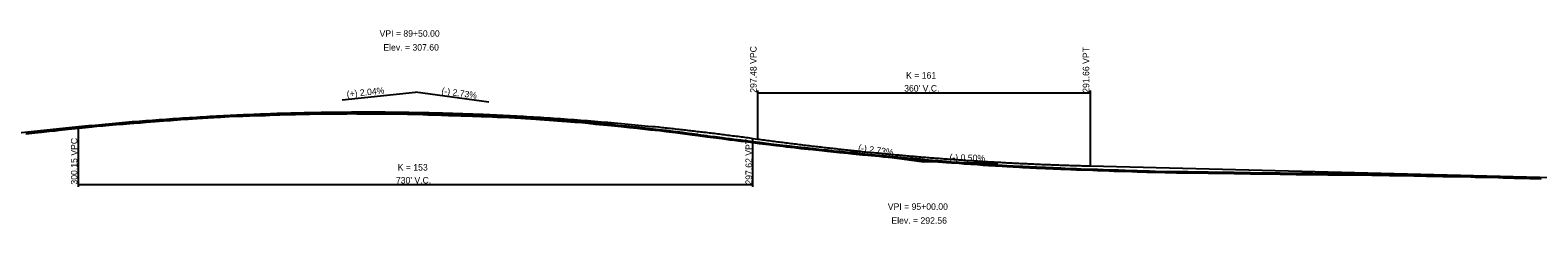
# Model space of a CAD drawing. Extents: x 1876258 to 1926563, y 729739 to 834437.
# Drawn here: x 1886896 to 1888528, y 831400 to 831609 of the extents above; entities that cross this region are included whole.
import ezdxf

# ---------------------------------------------------------------- set-up
doc = ezdxf.new("R2010")
doc.units = 0
for name, color, linetype in [('RD_EX_BldgApp', 7, 'Continuous'), ('RD_EX_H2O_BlueLn', 7, 'Continuous'), ('RD_EX_RailRoad', 7, 'Continuous'), ('RD_HC_Data', 7, 'Continuous'), ('RD_HC_Data_Tic', 7, 'Continuous'), ('RD_HC_TX_Sta50', 7, 'Continuous'), ('RD_PD_ALT5_CL', 7, 'Continuous')]:
    doc.layers.add(name, color=color, linetype=linetype)

msp = doc.modelspace()

# ---------------------------------------------------------------- linework, layer by layer
at = {"layer": 'RD_EX_BldgApp'}
for points in [[(1887021.4, 831509.8), (1887031.3, 831510.7), (1887040.1, 831511.4), (1887048, 831511.9), (1887059.2, 831512.8), (1887062.9, 831513), (1887067, 831513.3), (1887076.8, 831514), (1887082.4, 831514.4), (1887094.6, 831515.1), (1887102.1, 831515.5), (1887111.4, 831516), (1887118.9, 831516.3), (1887126.1, 831516.4), (1887133.8, 831516.7), (1887143.4, 831517), (1887150.5, 831517.3), (1887160.5, 831517.7), (1887166.2, 831517.9), (1887176, 831518.2), (1887183, 831518.3), (1887190.3, 831518.5), (1887198.6, 831518.7), (1887205.6, 831518.8), (1887212.8, 831518.9), (1887221.4, 831519), (1887228.5, 831519.1), (1887238.6, 831519.1), (1887243.3, 831519.2), (1887249.5, 831519.1), (1887254.4, 831519.1), (1887261.6, 831519.1), (1887266.4, 831519.1), (1887274.9, 831519.1), (1887282, 831519), (1887288.9, 831518.9), (1887294.2, 831518.8), (1887304.4, 831518.7), (1887311.7, 831518.4), (1887321.4, 831518.1), (1887326.5, 831518), (1887334.1, 831517.8), (1887341.1, 831517.6), (1887348.7, 831517.3), (1887355.6, 831517), (1887362.4, 831516.8), (1887370.9, 831516.6), (1887374.8, 831516.4), (1887384, 831516.2), (1887391.1, 831516.1), (1887401.4, 831515.5), (1887408, 831515.2), (1887420.4, 831514.6), (1887427, 831514.1), (1887432.1, 831513.9), (1887443.1, 831513.2), (1887447.6, 831512.9), (1887457.8, 831512.2), (1887466.7, 831511.5), (1887476.7, 831510.7), (1887485.4, 831510), (1887493.1, 831509.4), (1887499.8, 831508.7), (1887507.8, 831507.9), (1887516.5, 831507.2), (1887524.8, 831506.3), (1887535.7, 831505.1), (1887544.4, 831504.2), (1887552.7, 831503.4), (1887561.5, 831502.4), (1887567.2, 831501.8), (1887577.1, 831500.8), (1887584.4, 831500), (1887594.4, 831498.8), (1887601.8, 831497.7), (1887612.3, 831496.3), (1887618.7, 831495.5), (1887628.8, 831494.1), (1887635.1, 831493.4), (1887644.6, 831492.1), (1887646.7, 831491.8), (1887649, 831491.6), (1887653.3, 831491), (1887657.7, 831490.4), (1887665.1, 831489.5), (1887670, 831488.9), (1887678.2, 831487.8), (1887684.9, 831487), (1887695.4, 831485.6), (1887700.4, 831485), (1887710.5, 831483.8), (1887714.6, 831483.4), (1887723.3, 831482.4), (1887730.1, 831481.6), (1887737.9, 831480.8), (1887743.1, 831480.2), (1887752.7, 831479.3), (1887758.6, 831478.7), (1887765.5, 831477.9), (1887771.7, 831477.3), (1887780.9, 831476.3)], [(1886891.2, 831497.4), (1886901.2, 831498.5), (1886908.1, 831499.2), (1886917, 831500.1), (1886923.1, 831500.7), (1886927.4, 831501.2), (1886934, 831502), (1886940.6, 831502.7), (1886948.9, 831503.5), (1886955.8, 831504.2), (1886962.8, 831505), (1886968.2, 831505.5), (1886974.5, 831506.1), (1886981.6, 831506.8), (1886989.1, 831507.3), (1886996.7, 831507.9), (1887003.8, 831508.4), (1887008.2, 831508.9), (1887015.1, 831509.3), (1887021.4, 831509.8)], [(1887780.9, 831476.3), (1887786.3, 831475.7), (1887796.8, 831474.7), (1887802.4, 831474.2), (1887806.5, 831473.9), (1887814.7, 831473.1), (1887819.5, 831472.6), (1887829.4, 831471.6), (1887834.9, 831471.1), (1887844.8, 831470.3), (1887851, 831469.7), (1887859.2, 831468.9), (1887864.2, 831468.4), (1887872.3, 831467.7), (1887878.5, 831467.2), (1887887.7, 831466.4), (1887892.9, 831466), (1887901.2, 831465.5), (1887906.6, 831465), (1887921, 831464), (1887927.2, 831463.6), (1887933.1, 831463.2), (1887947.7, 831462.3), (1887953, 831462), (1887966.5, 831461.1), (1887970.2, 831460.9), (1887985, 831460.3), (1887989.9, 831460.1), (1887994.6, 831459.8), (1888011.5, 831459.1), (1888016.1, 831459), (1888028.4, 831458.5), (1888032.9, 831458.3), (1888046, 831457.9), (1888051.1, 831457.7), (1888063.7, 831457.3), (1888069, 831457.1), (1888073.8, 831457), (1888088.2, 831456.5), (1888093.8, 831456.3), (1888104.6, 831456), (1888107.3, 831455.9), (1888113.2, 831455.8), (1888124.4, 831455.4), (1888136.5, 831455.3), (1888142.8, 831455.2), (1888148.9, 831455.2), (1888164.5, 831455), (1888170.8, 831454.9), (1888181.8, 831454.7), (1888187, 831454.7), (1888199, 831454.4), (1888205.1, 831454.3), (1888216.7, 831454.2), (1888223, 831454.1), (1888233, 831454), (1888239.3, 831453.9), (1888248.8, 831453.7), (1888259.4, 831453.6), (1888266.1, 831453.5), (1888277.2, 831453.4), (1888284, 831453.3), (1888300.3, 831453.1), (1888307.8, 831453), (1888321.2, 831452.9), (1888327, 831452.9), (1888331.8, 831452.8), (1888348.1, 831452.6), (1888353.3, 831452.5), (1888367.1, 831452.3), (1888375.5, 831452.2), (1888393.4, 831451.9), (1888398.5, 831451.8), (1888407.2, 831451.6), (1888412.5, 831451.5), (1888424.8, 831451.3), (1888429.6, 831451.2), (1888439.4, 831451.1), (1888444.5, 831451), (1888455, 831450.7), (1888459.7, 831450.6), (1888471.1, 831450.4), (1888474.9, 831450.3), (1888485, 831450), (1888490, 831449.9), (1888501.9, 831449.4), (1888506.5, 831449.2), (1888531.2, 831448.7)]]:
    msp.add_lwpolyline(points, dxfattribs=at)
at = {"layer": 'RD_EX_H2O_BlueLn'}
for p, q in [((1887683.1, 831544.2), (1887683.1, 831491.7)), ((1887683.1, 831541.7), (1888043.1, 831541.7)), ((1888043.1, 831544.2), (1888043.1, 831462.6)), ((1886948.1, 831439.9), (1886948.1, 831505.1)), ((1887678.1, 831439.9), (1887678.1, 831492.4)), ((1886948.1, 831442.4), (1887678.1, 831442.4))]:
    msp.add_line(p, q, dxfattribs=at)
at = {"layer": 'RD_HC_Data_Tic'}
msp.add_lwpolyline([(1886891.1, 831498.7), (1886901, 831499.7), (1886908, 831500.4), (1886916.9, 831501.3), (1886923, 831501.9), (1886927.3, 831502.5), (1886933.9, 831503.2), (1886940.4, 831503.9), (1886948.7, 831504.8), (1886955.7, 831505.5), (1886962.7, 831506.2), (1886968.1, 831506.7), (1886974.3, 831507.4), (1886981.5, 831508), (1886989, 831508.5), (1886996.6, 831509.1), (1887003.7, 831509.7), (1887008.1, 831510.1), (1887015, 831510.5), (1887021.2, 831511), (1887031.2, 831512), (1887040, 831512.6), (1887047.9, 831513.2), (1887059.1, 831514.1), (1887062.8, 831514.3), (1887066.9, 831514.5), (1887072.4, 831514.9), (1887076.7, 831515.3), (1887081.9, 831515.6), (1887082.3, 831515.7), (1887091.5, 831516.2), (1887094.5, 831516.3), (1887101.1, 831516.7), (1887102, 831516.7), (1887110.7, 831517.2), (1887111.3, 831517.2), (1887118.9, 831517.6), (1887120.3, 831517.6), (1887126.1, 831517.7), (1887129.8, 831517.8), (1887133.7, 831518), (1887139.4, 831518.1), (1887143.4, 831518.2), (1887149, 831518.4), (1887150.4, 831518.5), (1887158.5, 831518.9), (1887160.4, 831518.9), (1887166.1, 831519.1), (1887168.1, 831519.2), (1887176, 831519.4), (1887177.7, 831519.5), (1887183, 831519.6), (1887187.3, 831519.7), (1887190.3, 831519.7), (1887196.8, 831519.9), (1887198.5, 831519.9), (1887205.6, 831520.1), (1887206.4, 831520.1), (1887212.8, 831520.1), (1887216, 831520.2), (1887221.4, 831520.2), (1887225.6, 831520.3), (1887228.5, 831520.3), (1887235.2, 831520.4), (1887238.6, 831520.4), (1887243.3, 831520.4), (1887244.7, 831520.4), (1887249.5, 831520.4), (1887254.3, 831520.4), (1887254.4, 831520.4), (1887261.6, 831520.4), (1887263.9, 831520.4), (1887266.4, 831520.3), (1887273.4, 831520.4), (1887275, 831520.4), (1887282.1, 831520.3), (1887283, 831520.3), (1887288.9, 831520.2), (1887292.6, 831520.1), (1887294.2, 831520.1), (1887302.2, 831519.9), (1887304.5, 831519.9), (1887311.7, 831519.7), (1887311.8, 831519.7), (1887321.3, 831519.4), (1887321.4, 831519.4), (1887326.5, 831519.3), (1887330.9, 831519.2), (1887334.1, 831519.1), (1887340.5, 831518.9), (1887341.2, 831518.8), (1887348.8, 831518.6), (1887350.1, 831518.5), (1887355.6, 831518.3), (1887359.6, 831518.2), (1887362.4, 831518.1), (1887369.2, 831517.9), (1887370.9, 831517.8), (1887374.9, 831517.7), (1887378.8, 831517.6), (1887384, 831517.5), (1887388.3, 831517.4), (1887391.1, 831517.3), (1887397.9, 831517), (1887401.4, 831516.8), (1887407.5, 831516.5), (1887408, 831516.4), (1887417.1, 831516), (1887420.5, 831515.9), (1887426.7, 831515.4), (1887427.1, 831515.4), (1887432.1, 831515.1), (1887436.2, 831514.9), (1887443.2, 831514.5), (1887445.8, 831514.3), (1887447.7, 831514.1), (1887455.4, 831513.6), (1887457.9, 831513.4), (1887465, 831512.9), (1887466.8, 831512.8), (1887474.5, 831512.1), (1887476.8, 831512), (1887484.1, 831511.4), (1887485.5, 831511.3), (1887493.2, 831510.6), (1887493.7, 831510.6), (1887499.9, 831509.9), (1887503.3, 831509.6), (1887507.9, 831509.2), (1887512.8, 831508.8), (1887516.6, 831508.4), (1887522.4, 831507.8), (1887524.9, 831507.6), (1887532, 831506.8), (1887535.8, 831506.4), (1887541.6, 831505.8), (1887544.6, 831505.5), (1887551.1, 831504.8), (1887552.9, 831504.7), (1887560.7, 831503.8), (1887561.7, 831503.7), (1887567.3, 831503.1), (1887570.3, 831502.8), (1887577.2, 831502.1), (1887579.9, 831501.8), (1887584.5, 831501.2), (1887589.4, 831500.6), (1887594.6, 831500), (1887599, 831499.4), (1887602, 831499), (1887608.6, 831498.1), (1887612.4, 831497.5), (1887618.2, 831496.8), (1887618.9, 831496.7), (1887627.8, 831495.5), (1887629, 831495.3), (1887635.3, 831494.6), (1887637.3, 831494.3), (1887644.8, 831493.3), (1887646.9, 831493.1), (1887649.2, 831492.8), (1887653.4, 831492.2), (1887657.8, 831491.7), (1887665.2, 831490.8), (1887670.1, 831490.1), (1887678.3, 831489.1), (1887685.1, 831488.3), (1887695.5, 831486.9), (1887700.6, 831486.3), (1887710.6, 831485), (1887714.7, 831484.7), (1887723.4, 831483.7), (1887730.2, 831482.9), (1887738.1, 831482), (1887743.2, 831481.4), (1887752.8, 831480.5), (1887758.8, 831479.9), (1887765.6, 831479.1), (1887771.8, 831478.5), (1887781.1, 831477.6), (1887786.5, 831477), (1887797, 831476), (1887802.5, 831475.4), (1887806.6, 831475.1), (1887814.8, 831474.4), (1887819.6, 831473.9), (1887829.6, 831472.9), (1887835, 831472.3), (1887844.9, 831471.5), (1887851.1, 831470.9), (1887859.4, 831470.1), (1887864.3, 831469.7), (1887872.4, 831469), (1887878.6, 831468.5), (1887887.8, 831467.7), (1887893, 831467.2), (1887901.3, 831466.7), (1887906.7, 831466.3), (1887921.1, 831465.2), (1887927.3, 831464.9), (1887933.2, 831464.4), (1887947.8, 831463.5), (1887953.1, 831463.2), (1887966.6, 831462.4), (1887970.3, 831462.2), (1887985, 831461.5), (1887990, 831461.3), (1887994.6, 831461.1), (1888011.5, 831460.4), (1888016.1, 831460.2), (1888028.4, 831459.7), (1888033, 831459.6), (1888046.1, 831459.2), (1888051.1, 831459), (1888063.7, 831458.5), (1888069, 831458.3), (1888073.8, 831458.2), (1888088.2, 831457.8), (1888093.9, 831457.6), (1888104.6, 831457.3), (1888107.3, 831457.2), (1888113.3, 831457), (1888124.4, 831456.7), (1888136.5, 831456.5), (1888142.9, 831456.5), (1888148.9, 831456.4), (1888164.5, 831456.3), (1888170.8, 831456.1), (1888181.8, 831455.9), (1888187, 831455.9), (1888199, 831455.7), (1888205.1, 831455.6), (1888216.7, 831455.4), (1888223, 831455.3), (1888233, 831455.2), (1888239.3, 831455.1), (1888248.9, 831455), (1888259.4, 831454.9), (1888266.1, 831454.8), (1888277.2, 831454.6), (1888284, 831454.6), (1888300.3, 831454.3), (1888307.8, 831454.2), (1888321.2, 831454.2), (1888327, 831454.1), (1888331.8, 831454.1), (1888348.1, 831453.9), (1888353.3, 831453.8), (1888367.1, 831453.5), (1888375.5, 831453.4), (1888393.4, 831453.2), (1888398.6, 831453.1), (1888407.2, 831452.8), (1888412.5, 831452.7), (1888424.8, 831452.5), (1888429.7, 831452.4), (1888439.4, 831452.3), (1888444.5, 831452.2), (1888455, 831452), (1888459.7, 831451.9), (1888471.1, 831451.6), (1888474.9, 831451.5), (1888485.1, 831451.3), (1888490, 831451.1), (1888501.9, 831450.6), (1888506.5, 831450.5), (1888531.2, 831449.9)], dxfattribs=at)
at = {"layer": 'RD_HC_TX_Sta50'}
for p, q in [((1887233.5, 831534.2), (1887313.1, 831542.3)), ((1887392.3, 831531.5), (1887313.1, 831542.3)), ((1887783.8, 831477.9), (1887863.1, 831467.1)), ((1887943.1, 831465.1), (1887863.1, 831467.1))]:
    msp.add_line(p, q, dxfattribs=at)
at = {"layer": 'RD_PD_ALT5_CL'}
for p, q in [((1886841, 831494.1), (1886948.1, 831505.1)), ((1887678.1, 831492.4), (1887683.1, 831491.7)), ((1888043.1, 831462.6), (1888558.1, 831449.7))]:
    msp.add_line(p, q, dxfattribs=at)
for points in [[(1886948.1, 831505.1), (1886962.7, 831506.5), (1886977.3, 831507.9), (1886991.9, 831509.2), (1887006.5, 831510.5), (1887021.1, 831511.6), (1887035.7, 831512.7), (1887050.3, 831513.8), (1887064.9, 831514.7), (1887079.5, 831515.6), (1887094.1, 831516.5), (1887108.7, 831517.2), (1887123.3, 831517.9), (1887137.9, 831518.5), (1887152.5, 831519.1), (1887167.1, 831519.6), (1887181.7, 831520), (1887196.3, 831520.3), (1887210.9, 831520.6), (1887225.5, 831520.8), (1887240.1, 831520.9), (1887254.7, 831521), (1887269.3, 831521), (1887283.9, 831520.9), (1887298.5, 831520.7), (1887313.1, 831520.5), (1887327.7, 831520.2), (1887342.3, 831519.9), (1887356.9, 831519.4), (1887371.5, 831518.9), (1887386.1, 831518.4), (1887400.7, 831517.7), (1887415.3, 831517), (1887429.9, 831516.3), (1887444.5, 831515.4), (1887459.1, 831514.5), (1887473.7, 831513.5), (1887488.3, 831512.4), (1887502.9, 831511.3), (1887517.5, 831510.1), (1887532.1, 831508.9), (1887546.7, 831507.5), (1887561.3, 831506.1), (1887575.9, 831504.7), (1887590.5, 831503.1), (1887605.1, 831501.5), (1887619.7, 831499.8), (1887634.3, 831498.1), (1887648.9, 831496.2), (1887663.5, 831494.4), (1887678.1, 831492.4)], [(1887683.1, 831491.7), (1887690.3, 831490.7), (1887697.5, 831489.8), (1887704.7, 831488.8), (1887711.9, 831487.9), (1887719.1, 831487), (1887726.3, 831486.1), (1887733.5, 831485.2), (1887740.7, 831484.3), (1887747.9, 831483.5), (1887755.1, 831482.7), (1887762.3, 831481.9), (1887769.5, 831481.1), (1887776.7, 831480.3), (1887783.9, 831479.5), (1887791.1, 831478.8), (1887798.3, 831478), (1887805.5, 831477.3), (1887812.7, 831476.6), (1887819.9, 831475.9), (1887827.1, 831475.2), (1887834.3, 831474.6), (1887841.5, 831473.9), (1887848.7, 831473.3), (1887855.9, 831472.7), (1887863.1, 831472.1), (1887870.3, 831471.5), (1887877.5, 831471), (1887884.7, 831470.4), (1887891.9, 831469.9), (1887899.1, 831469.4), (1887906.3, 831468.9), (1887913.5, 831468.4), (1887920.7, 831468), (1887927.9, 831467.5), (1887935.1, 831467.1), (1887942.3, 831466.7), (1887949.5, 831466.3), (1887956.7, 831465.9), (1887963.9, 831465.5), (1887971.1, 831465.2), (1887978.3, 831464.9), (1887985.5, 831464.6), (1887992.7, 831464.2), (1887999.9, 831464), (1888007.1, 831463.7), (1888014.3, 831463.4), (1888021.5, 831463.2), (1888028.7, 831463), (1888035.9, 831462.8), (1888043.1, 831462.6)]]:
    msp.add_spline(points, degree=3, dxfattribs=at)

# ---------------------------------------------------------------- texts
at = {"layer": 'RD_EX_H2O_BlueLn'}
for s, p in [('K = 161', (1887843.9, 831557)), ("360' V.C.", (1887841.8, 831543)), ('K = 153', (1887293.7, 831457.6)), ("730' V.C.", (1887291.8, 831443.6))]:
    msp.add_text(s, height=7, dxfattribs=at).set_placement(p)
at = {"layer": 'RD_EX_RailRoad'}
for s, p in [('297.48 VPC', (1887682.1, 831541.7)), ('291.66 VPT', (1888042.1, 831541.7)), ('300.15 VPC', (1886947.1, 831442.4)), ('297.62 VPT', (1887677.1, 831442.4))]:
    msp.add_text(s, height=7, rotation=90, dxfattribs=at).set_placement(p)
at = {"layer": 'RD_HC_Data'}
for s, p in [('VPI = 89+50.00', (1887274.1, 831602.3)), ('Elev. = 307.60', (1887278.2, 831587.3)), ('VPI = 95+00.00', (1887824.1, 831415.1)), ('Elev. = 292.56', (1887828, 831400.1))]:
    msp.add_text(s, height=7, dxfattribs=at).set_placement(p)
at = {"layer": 'RD_HC_TX_Sta50'}
for s, rotation, p in [('(+) 2.04%', 5.8261, (1887238.9, 831536.7)), ('(-) 2.73%', 352.2144, (1887340.8, 831540.5)), ('(-) 2.73%', 352.2144, (1887791.7, 831478.9)), ('(-) 0.50%', 358.5679, (1887890.8, 831468.4))]:
    msp.add_text(s, height=7, rotation=rotation, dxfattribs=at).set_placement(p)

doc.saveas('drawing.dxf')
